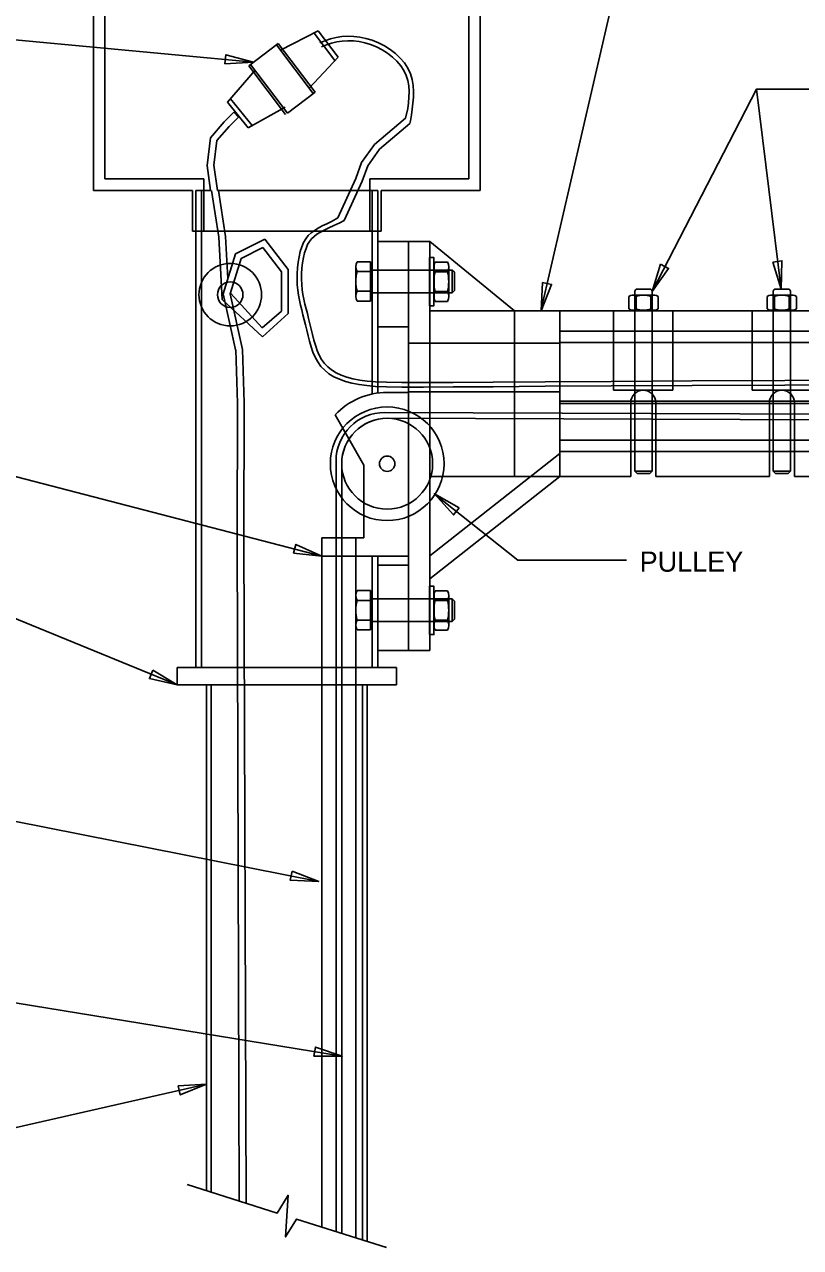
# Model space of a CAD drawing. Extents: x 1299104.6 to 1299141.4, y 239713.3 to 239735.3.
# Drawn here: x 1299115.78 to 1299120.38, y 239723.02 to 239730.29 of the extents above; entities that cross this region are included whole.
import ezdxf

# ---------------------------------------------------------------- set-up
doc = ezdxf.new("R2010")
doc.units = 0
for name, color, linetype in [('Default', 7, 'Continuous'), ('DIM TXT', 7, 'Continuous'), ('Level 3', 7, 'Continuous'), ('Level 5', 7, 'Continuous'), ('Level 6', 7, 'Continuous'), ('Level 8', 7, 'Continuous')]:
    doc.layers.add(name, color=color, linetype=linetype)

# ---------------------------------------------------------------- blocks, each defined once
blk = doc.blocks.new('BOLTS')
at = {"layer": 'Default'}
for p, q in [((-1.5, 0), (-1.5, 17.41)), ((-1.1, 17.81), (1.1, 17.81)), ((1.5, 17.41), (1.5, 0)), ((-1.95, 16.76), (1.95, 16.76)), ((-1.3, 16.52), (-1.3, 14.31)), ((1.3, 16.52), (1.3, 14.31)), ((1.95, 14.07), (-1.95, 14.07)), ((-1.5, -14.24), (-1.5, 0)), ((1.5, 0), (1.5, -14.24)), ((-1.5, -14.24), (1.5, -14.24)), ((-1.1, -14.64), (-1.5, -14.24)), ((1.1, -14.64), (-1.1, -14.64)), ((1.5, -14.24), (1.1, -14.64))]:
    blk.add_line(p, q, dxfattribs=at)
for points in [[(-2.6, 14.31), (-2.6, 16.52)], [(2.6, 16.52), (2.6, 14.31)]]:
    blk.add_lwpolyline(points, dxfattribs=at)
for centre, radius, start, end in [((-1.1, 17.41), 0.4, 90, 180), ((1.1, 17.41), 0.4, 0, 90), ((-1.95, 15.76), 1, 49.4687, 130.5313), ((0, 13.12), 3.64, 69.0802, 110.9198), ((1.95, 15.76), 1, 49.4687, 130.5314), ((-1.95, 15.07), 1, 229.4687, 310.5314), ((0, 17.71), 3.64, 249.0802, 290.9198), ((1.95, 15.07), 1, 229.4687, 310.5313)]:
    blk.add_arc(centre, radius, start, end, dxfattribs=at)

msp = doc.modelspace()

# ---------------------------------------------------------------- linework, layer by layer
at = {"layer": 'Level 3'}
for p, q in [((1299116.1867, 239729.3002), (1299116.1867, 239730.9202)), ((1299116.2542, 239729.3677), (1299116.2542, 239730.9202)), ((1299118.4142, 239729.3677), (1299118.4142, 239730.9202)), ((1299118.4817, 239729.3002), (1299118.4817, 239730.9202)), ((1299117.2964, 239730.1324), (1299117.5205, 239730.2472)), ((1299117.4961, 239730.2347), (1299117.6196, 239730.0715)), ((1299117.5205, 239730.2472), (1299117.6382, 239730.0916)), ((1299117.2831, 239730.1725), (1299117.1077, 239730.0397)), ((1299117.2723, 239730.1643), (1299117.491, 239729.8753)), ((1299117.2831, 239730.1725), (1299117.5018, 239729.8835)), ((1299117.1184, 239730.0479), (1299117.3371, 239729.7589)), ((1299117.4669, 239729.9072), (1299117.6382, 239730.0916)), ((1299117.1459, 239730.0141), (1299116.9815, 239729.8234)), ((1299117.1077, 239730.0397), (1299117.3263, 239729.7507)), ((1299116.9994, 239729.8442), (1299117.1289, 239729.6857)), ((1299117.5018, 239729.8835), (1299117.3371, 239729.7589)), ((1299116.9621, 239729.7081), (1299117.0186, 239729.7645)), ((1299116.9815, 239729.8234), (1299117.105, 239729.6723)), ((1299117.0186, 239729.7645), (1299117.0472, 239729.7359)), ((1299117.3246, 239729.7953), (1299117.105, 239729.6723)), ((1299116.9918, 239729.6805), (1299117.0472, 239729.7359)), ((1299116.8602, 239729.4488), (1299116.8799, 239729.6128)), ((1299116.9186, 239729.5957), (1299116.9918, 239729.6805)), ((1299116.901, 239729.4493), (1299116.9186, 239729.5957)), ((1299116.8814, 239729.3002), (1299116.8602, 239729.4488)), ((1299116.9223, 239729.3002), (1299116.901, 239729.4493)), ((1299116.8419, 239729.3677), (1299116.2542, 239729.3677)), ((1299116.8419, 239729.0572), (1299116.8419, 239729.3677)), ((1299117.8265, 239729.0572), (1299117.8265, 239729.3677)), ((1299118.4142, 239729.3677), (1299117.8265, 239729.3677)), ((1299116.7744, 239729.3002), (1299116.1867, 239729.3002)), ((1299116.7744, 239729.0572), (1299116.7744, 239729.3002)), ((1299116.8814, 239729.3002), (1299116.7942, 239729.3002)), ((1299116.7942, 239729.3002), (1299116.7942, 239726.4653)), ((1299116.8269, 239729.3002), (1299116.8269, 239726.4653)), ((1299116.9301, 239729.0213), (1299116.8864, 239729.3002)), ((1299117.8742, 239729.3002), (1299116.9223, 239729.3002)), ((1299116.9704, 239729.0256), (1299116.9274, 239729.3002)), ((1299117.8416, 239729.3002), (1299117.8416, 239728.0908)), ((1299117.8742, 239729.3002), (1299117.8742, 239728.0964)), ((1299117.894, 239729.0572), (1299117.894, 239729.3002)), ((1299118.4817, 239729.3002), (1299117.894, 239729.3002)), ((1299117.894, 239729.0572), (1299116.7744, 239729.0572)), ((1299116.9506, 239728.6512), (1299116.9301, 239729.0213)), ((1299116.9842, 239728.7771), (1299116.9704, 239729.0256)), ((1299117.0288, 239728.9234), (1299117.2042, 239729.0109)), ((1299117.0625, 239728.8949), (1299117.1923, 239728.9598)), ((1299117.1923, 239728.9598), (1299117.302, 239728.8165)), ((1299117.2042, 239729.0109), (1299117.3425, 239728.8302)), ((1299118.0557, 239728.9965), (1299117.8742, 239728.9965)), ((1299118.0557, 239726.5665), (1299118.0557, 239728.9965)), ((1299118.1826, 239728.9965), (1299118.0557, 239728.9965)), ((1299118.1826, 239728.9965), (1299118.6854, 239728.5854)), ((1299118.1826, 239726.5665), (1299118.1826, 239728.9965)), ((1299116.9566, 239728.6864), (1299117.0288, 239728.9234)), ((1299116.9984, 239728.6848), (1299117.0625, 239728.8949)), ((1299117.302, 239728.8165), (1299117.302, 239728.5832)), ((1299117.3425, 239728.8302), (1299117.3425, 239728.5681)), ((1299117.7433, 239728.6717), (1299117.7433, 239728.847)), ((1299117.7527, 239728.8178), (1299117.8311, 239728.8178)), ((1299117.8308, 239728.6424), (1299117.8308, 239728.8763)), ((1299117.8416, 239728.8516), (1299117.8308, 239728.8516)), ((1299117.8416, 239728.8268), (1299118.3166, 239728.8268)), ((1299118.2083, 239728.8454), (1299118.2083, 239728.67)), ((1299118.215, 239728.8161), (1299118.2887, 239728.8161)), ((1299118.2955, 239728.67), (1299118.2955, 239728.8454)), ((1299118.3166, 239728.6918), (1299118.3166, 239728.8268)), ((1299118.3166, 239728.8268), (1299118.3301, 239728.8133)), ((1299118.3301, 239728.8133), (1299118.3301, 239728.7053)), ((1299117.0322, 239728.3457), (1299116.9566, 239728.6864)), ((1299117.0718, 239728.3545), (1299116.9984, 239728.6848)), ((1299117.1879, 239728.4843), (1299117.0012, 239728.6874)), ((1299117.7527, 239728.7009), (1299117.8311, 239728.7009)), ((1299117.8416, 239728.6671), (1299117.8308, 239728.6671)), ((1299118.3166, 239728.6918), (1299117.8416, 239728.6918)), ((1299118.215, 239728.6992), (1299118.2887, 239728.6992)), ((1299118.3166, 239728.6918), (1299118.3301, 239728.7053)), ((1299117.1898, 239728.4308), (1299116.9506, 239728.6512)), ((1299117.302, 239728.5832), (1299117.1879, 239728.4843)), ((1299117.3425, 239728.5681), (1299117.1898, 239728.4308)), ((1299118.1826, 239728.5854), (1299120.6126, 239728.5854)), ((1299118.6854, 239727.5999), (1299118.6854, 239728.5854)), ((1299118.9548, 239727.5999), (1299118.9548, 239728.5854)), ((1299119.2745, 239728.5854), (1299119.2745, 239728.1129)), ((1299119.626, 239728.5854), (1299119.626, 239728.1129)), ((1299120.098, 239728.5854), (1299120.098, 239728.1129)), ((1299118.0557, 239728.4902), (1299117.8742, 239728.4902)), ((1299117.93, 239728.1001), (1299118.0557, 239728.1001)), ((1299119.2745, 239728.1129), (1299119.626, 239728.1129)), ((1299119.376, 239728.1129), (1299119.5245, 239728.1129)), ((1299120.098, 239728.1129), (1299120.4495, 239728.1129)), ((1299119.376, 239727.5999), (1299119.376, 239728.0387)), ((1299119.5245, 239727.5999), (1299119.5245, 239728.0387)), ((1299120.1995, 239727.5999), (1299120.1995, 239728.0387)), ((1299120.348, 239727.5999), (1299120.348, 239728.0387)), ((1299119.5245, 239727.7484), (1299119.376, 239727.7484)), ((1299120.348, 239727.7484), (1299120.1995, 239727.7484)), ((1299118.1826, 239726.9924), (1299118.9548, 239727.5999)), ((1299118.1826, 239727.5999), (1299119.376, 239727.5999)), ((1299119.5245, 239727.5999), (1299120.1995, 239727.5999)), ((1299120.348, 239727.5999), (1299120.6126, 239727.5999)), ((1299117.5427, 239727.1281), (1299117.5427, 239727.2361)), ((1299117.7433, 239727.2361), (1299117.7433, 239723.0777)), ((1299117.5427, 239727.1281), (1299117.5427, 239723.1411)), ((1299117.5427, 239727.1281), (1299117.7433, 239727.1281)), ((1299117.8416, 239727.1281), (1299117.8416, 239726.4653)), ((1299117.8742, 239727.1281), (1299117.8742, 239726.4653)), ((1299118.0557, 239727.0728), (1299117.8742, 239727.0728)), ((1299117.8308, 239726.6894), (1299117.8308, 239726.9232)), ((1299117.7433, 239726.7186), (1299117.7433, 239726.8939)), ((1299117.7527, 239726.8647), (1299117.8311, 239726.8647)), ((1299117.8416, 239726.8985), (1299117.8308, 239726.8985)), ((1299117.8416, 239726.8738), (1299118.3166, 239726.8738)), ((1299118.2083, 239726.8923), (1299118.2083, 239726.7169)), ((1299118.215, 239726.8631), (1299118.2887, 239726.8631)), ((1299118.2955, 239726.7169), (1299118.2955, 239726.8923)), ((1299118.3166, 239726.7388), (1299118.3166, 239726.8738)), ((1299118.3166, 239726.8738), (1299118.3301, 239726.8603)), ((1299118.3301, 239726.8603), (1299118.3301, 239726.7523)), ((1299117.7527, 239726.7478), (1299117.8311, 239726.7478)), ((1299117.8416, 239726.7141), (1299117.8308, 239726.7141)), ((1299118.3166, 239726.7388), (1299117.8416, 239726.7388)), ((1299118.215, 239726.7461), (1299118.2887, 239726.7461)), ((1299118.3166, 239726.7388), (1299118.3301, 239726.7523)), ((1299118.0557, 239726.5665), (1299117.8742, 239726.5665)), ((1299118.1826, 239726.5665), (1299118.0557, 239726.5665)), ((1299117.986, 239726.4653), (1299116.6824, 239726.4653)), ((1299116.6824, 239726.3627), (1299116.6824, 239726.4653)), ((1299117.986, 239726.4653), (1299117.986, 239726.3627)), ((1299117.986, 239726.3627), (1299116.6824, 239726.3627)), ((1299116.8576, 239726.3627), (1299116.8576, 239723.3577)), ((1299116.8846, 239726.3627), (1299116.8846, 239723.3491)), ((1299117.7839, 239726.3627), (1299117.7839, 239723.0649)), ((1299117.8109, 239726.3627), (1299117.8109, 239723.0564))]:
    msp.add_line(p, q, dxfattribs=at)
for points in [[(1299117.5296, 239730.1771), (1299117.5604, 239730.1894), (1299117.593, 239730.1999), (1299117.6263, 239730.208), (1299117.6605, 239730.2134), (1299117.6955, 239730.2159), (1299117.7311, 239730.2151), (1299117.7674, 239730.211), (1299117.8041, 239730.2031), (1299117.8411, 239730.1916), (1299117.8777, 239730.1765), (1299117.9133, 239730.1582), (1299117.9472, 239730.1369), (1299117.9789, 239730.1128), (1299118.0077, 239730.0862), (1299118.0328, 239730.0571), (1299118.0534, 239730.0256), (1299118.0687, 239729.9924), (1299118.0789, 239729.9582), (1299118.0847, 239729.9233), (1299118.0868, 239729.8882), (1299118.0861, 239729.8529), (1299118.0832, 239729.8177), (1299118.0788, 239729.7826), (1299118.0736, 239729.7479), (1299118.0681, 239729.7133), (1299118.0655, 239729.6983)], [(1299117.5396, 239730.152), (1299117.5696, 239730.164), (1299117.6003, 239730.1739), (1299117.6316, 239730.1815), (1299117.6636, 239730.1865), (1299117.6962, 239730.1888), (1299117.7293, 239730.1882), (1299117.763, 239730.1843), (1299117.7973, 239730.177), (1299117.8319, 239730.1661), (1299117.8664, 239730.1519), (1299117.8999, 239730.1347), (1299117.9319, 239730.1147), (1299117.9615, 239730.0921), (1299117.9882, 239730.0674), (1299118.0112, 239730.0408), (1299118.0297, 239730.0125), (1299118.0434, 239729.9829), (1299118.0526, 239729.9521), (1299118.0578, 239729.9203), (1299118.0598, 239729.8876), (1299118.0591, 239729.8543), (1299118.0563, 239729.8205), (1299118.0521, 239729.7863), (1299118.0393, 239729.7292), (1299118.0521, 239729.7863), (1299118.0521, 239729.7863), (1299118.0393, 239729.7292)], [(1299116.8799, 239729.6128), (1299116.9621, 239729.7081)], [(1299117.6374, 239729.1374), (1299117.744, 239729.3706), (1299117.7783, 239729.4647), (1299117.8545, 239729.5721), (1299118.0393, 239729.7292)], [(1299117.6742, 239729.1205), (1299117.7816, 239729.3552), (1299117.8145, 239729.4457), (1299117.8846, 239729.5445), (1299118.0655, 239729.6983)], [(1299117.6026, 239729.1164), (1299117.6026, 239729.1164), (1299117.6374, 239729.1374), (1299117.6026, 239729.1164), (1299117.572, 239729.1021), (1299117.5444, 239729.0887), (1299117.5197, 239729.0756), (1299117.4977, 239729.0621), (1299117.4782, 239729.0474), (1299117.4612, 239729.0311), (1299117.4463, 239729.0123), (1299117.4335, 239728.9905), (1299117.4226, 239728.9651), (1299117.4136, 239728.9366), (1299117.4064, 239728.9057), (1299117.4009, 239728.8731), (1299117.3972, 239728.8394), (1299117.3952, 239728.8053), (1299117.3949, 239728.7715), (1299117.3963, 239728.7386), (1299117.3992, 239728.7071), (1299117.4035, 239728.6769), (1299117.4089, 239728.6475), (1299117.4152, 239728.6187), (1299117.4223, 239728.59), (1299117.4297, 239728.561), (1299117.4374, 239728.5315), (1299117.445, 239728.5009), (1299117.4525, 239728.4692), (1299117.4601, 239728.4367), (1299117.4685, 239728.4039), (1299117.4779, 239728.3714), (1299117.489, 239728.3397), (1299117.5022, 239728.3093), (1299117.518, 239728.2808), (1299117.5367, 239728.2547), (1299117.5589, 239728.2315), (1299117.5845, 239728.2111), (1299117.6135, 239728.1933), (1299117.646, 239728.1782), (1299117.6818, 239728.1654), (1299117.7209, 239728.1549), (1299117.7633, 239728.1466), (1299117.809, 239728.1402), (1299117.8598, 239728.1358), (1299117.9252, 239728.133), (1299118.0166, 239728.1316), (1299118.1453, 239728.1314), (1299118.3227, 239728.1323), (1299118.5602, 239728.1339), (1299118.8691, 239728.1361), (1299119.2609, 239728.1386), (1299119.7409, 239728.1412), (1299120.2913, 239728.1437), (1299120.8881, 239728.1458)], [(1299117.6742, 239729.1205), (1299117.6479, 239729.1079), (1299117.6141, 239729.092), (1299117.5836, 239729.0777), (1299117.5566, 239729.0646), (1299117.5331, 239729.0521), (1299117.5129, 239729.0397), (1299117.4957, 239729.0268), (1299117.4812, 239729.0129), (1299117.4687, 239728.9971), (1299117.4577, 239728.9783), (1299117.448, 239728.9557), (1299117.4396, 239728.9295), (1299117.4328, 239728.9004), (1299117.4277, 239728.8694), (1299117.4241, 239728.8371), (1299117.4222, 239728.8044), (1299117.4219, 239728.7719), (1299117.4232, 239728.7403), (1299117.426, 239728.7102), (1299117.4301, 239728.6812), (1299117.4354, 239728.6529), (1299117.4415, 239728.6248), (1299117.4484, 239728.5965), (1299117.4559, 239728.5678), (1299117.4635, 239728.5381), (1299117.4712, 239728.5073), (1299117.4787, 239728.4754), (1299117.4863, 239728.4431), (1299117.4945, 239728.411), (1299117.5037, 239728.3796), (1299117.5142, 239728.3495), (1299117.5265, 239728.3212), (1299117.5408, 239728.2953), (1299117.5575, 239728.272), (1299117.5771, 239728.2515), (1299117.6, 239728.2332), (1299117.6263, 239728.2172), (1299117.6563, 239728.2032), (1299117.6898, 239728.1912), (1299117.727, 239728.1812), (1299117.7678, 239728.1732), (1299117.8121, 239728.1671), (1299117.8616, 239728.1627), (1299117.926, 239728.1599), (1299118.0168, 239728.1586), (1299118.1452, 239728.1584), (1299118.3225, 239728.1593), (1299118.56, 239728.1609), (1299118.8689, 239728.1631), (1299119.2607, 239728.1656), (1299119.7408, 239728.1682), (1299120.2912, 239728.1707), (1299120.888, 239728.1728)], [(1299117.7527, 239728.8763), (1299117.8308, 239728.8763)], [(1299117.8416, 239728.8516), (1299117.8416, 239728.6671)], [(1299118.215, 239728.8746), (1299118.2887, 239728.8746)], [(1299117.8308, 239728.6424), (1299117.7527, 239728.6424)], [(1299118.2887, 239728.6408), (1299118.215, 239728.6408)], [(1299117.7527, 239726.9232), (1299117.8308, 239726.9232)], [(1299118.215, 239726.9215), (1299118.2887, 239726.9215)], [(1299117.8416, 239726.8985), (1299117.8416, 239726.7141)], [(1299117.8308, 239726.6894), (1299117.7527, 239726.6894)], [(1299118.2887, 239726.6877), (1299118.215, 239726.6877)]]:
    msp.add_lwpolyline(points, dxfattribs=at)
for points in [[(1299118.1816, 239728.6143), (1299118.1816, 239728.901), (1299118.2073, 239728.901), (1299118.2073, 239728.6143)], [(1299118.1816, 239726.6612), (1299118.1816, 239726.948), (1299118.2073, 239726.948), (1299118.2073, 239726.6612)]]:
    msp.add_lwpolyline(points, close=True, dxfattribs=at)
for centre, radius in [((1299116.9979, 239728.6805), 0.1858), ((1299116.9979, 239728.6805), 0.0759), ((1299117.93, 239727.6762), 0.0459)]:
    msp.add_circle(centre, radius, dxfattribs=at)
for centre, radius, start, end in [((1299117.7932, 239728.847), 0.0499, 144.1655, 215.8345), ((1299117.9288, 239728.7593), 0.1855, 161.6338, 198.3662), ((1299118.2749, 239728.8454), 0.0667, 153.9914, 206.0086), ((1299118.4647, 239728.7577), 0.2565, 166.826, 193.174), ((1299118.2288, 239728.8454), 0.0667, 333.9913, 26.00868), ((1299118.039, 239728.7577), 0.2565, 346.826, 13.17401), ((1299117.7932, 239728.6717), 0.0499, 144.1654, 215.8346), ((1299118.2749, 239728.67), 0.0667, 153.9913, 206.0087), ((1299118.2288, 239728.67), 0.0667, 333.9914, 26.00863), ((1299119.4503, 239728.0387), 0.0742, 0, 180), ((1299120.2738, 239728.0387), 0.0742, 0, 180), ((1299117.93, 239727.6762), 0.27, 89.81051, 180), ((1299117.7932, 239726.8939), 0.0499, 144.1655, 215.8345), ((1299118.2749, 239726.8923), 0.0667, 153.9914, 206.0086), ((1299118.2288, 239726.8923), 0.0667, 333.9913, 26.00868), ((1299117.9288, 239726.8063), 0.1855, 161.6338, 198.3662), ((1299118.4647, 239726.8046), 0.2565, 166.826, 193.174), ((1299118.039, 239726.8046), 0.2565, 346.826, 13.17401), ((1299117.7932, 239726.7186), 0.0499, 144.1654, 215.8346), ((1299118.2749, 239726.7169), 0.0667, 153.9913, 206.0087), ((1299118.2288, 239726.7169), 0.0667, 333.9914, 26.00863)]:
    msp.add_arc(centre, radius, start, end, dxfattribs=at)
at = {"layer": 'Level 5'}
for p, q in [((1299117.0408, 239728.0367), (1299117.0313, 239728.3536)), ((1299117.0813, 239728.0376), (1299117.0718, 239728.3545)), ((1299117.0388, 239727.2436), (1299117.0408, 239728.0377)), ((1299117.0793, 239727.2435), (1299117.0813, 239728.0376)), ((1299117.0516, 239723.2963), (1299117.0388, 239727.2433)), ((1299117.0921, 239723.2835), (1299117.0793, 239727.2435))]:
    msp.add_line(p, q, dxfattribs=at)
at = {"layer": 'Level 6'}
for p, q in [((1299120.6126, 239728.4639), (1299118.9548, 239728.4639)), ((1299118.0557, 239728.393), (1299118.9548, 239728.393)), ((1299120.6126, 239728.3964), (1299118.9548, 239728.3964)), ((1299118.0557, 239728.1029), (1299118.9548, 239728.1029)), ((1299124.3548, 239728.0482), (1299118.9548, 239728.0482)), ((1299124.3548, 239728.0347), (1299118.9548, 239728.0347)), ((1299117.7923, 239727.6681), (1299117.6213, 239727.9667)), ((1299117.9141, 239727.98), (1299124.7722, 239727.9573)), ((1299117.9309, 239727.9462), (1299124.7553, 239727.9236)), ((1299120.6126, 239727.8159), (1299118.9548, 239727.8159)), ((1299118.1826, 239727.1298), (1299118.9548, 239727.7373)), ((1299120.6126, 239727.7484), (1299118.9548, 239727.7484)), ((1299117.6262, 239727.6931), (1299117.6262, 239723.1147)), ((1299117.66, 239727.6762), (1299117.66, 239723.1041)), ((1299117.7923, 239727.2361), (1299117.7923, 239727.6681)), ((1299117.5427, 239727.2361), (1299117.7923, 239727.2361)), ((1299117.5427, 239727.1281), (1299118.0557, 239727.1281))]:
    msp.add_line(p, q, dxfattribs=at)
for radius in [0.3375, 0.27]:
    msp.add_circle((1299117.93, 239727.6762), radius, dxfattribs=at)
for centre, radius, start, end in [((1299117.93, 239727.6762), 0.4239, 90, 136.74441), ((1299117.9131, 239727.6931), 0.2869, 89.81051, 180)]:
    msp.add_arc(centre, radius, start, end, dxfattribs=at)
at = {"layer": 'Level 8'}
for points in [[(1299118.8433, 239728.5854), (1299119.272, 239730.4433), (1299120.8021, 239730.4433)], [(1299117.1354, 239730.0607), (1299117.1354, 239730.0607), (1299114.8082, 239730.2803), (1299112.852, 239730.2803)], [(1299119.5029, 239728.6996), (1299119.5029, 239728.6996), (1299120.1241, 239729.9022), (1299120.793, 239729.9022)], [(1299120.2704, 239728.7139), (1299120.1241, 239729.9022), (1299120.8021, 239729.9022)], [(1299117.5427, 239727.1281), (1299113.6708, 239728.1331), (1299111.4228, 239728.1331), (1299111.4351, 239728.1331)], [(1299118.2098, 239727.4983), (1299118.2098, 239727.4983), (1299118.7066, 239727.1026), (1299119.3507, 239727.1026)], [(1299116.6824, 239726.3627), (1299114.9168, 239727.086)], [(1299117.5236, 239725.1938), (1299113.493, 239725.993), (1299111.3748, 239725.993)], [(1299117.6635, 239724.1563), (1299117.6635, 239724.1563), (1299114.3474, 239724.6972), (1299111.173, 239724.6972)], [(1299116.8576, 239723.9908), (1299115.4379, 239723.667), (1299111.4055, 239723.667)], [(1299116.7432, 239723.3938), (1299117.277, 239723.2251), (1299117.3418, 239723.3305), (1299117.3267, 239723.0836), (1299117.3914, 239723.1889), (1299117.9253, 239723.0202)]]:
    msp.add_lwpolyline(points, dxfattribs=at)
for points in [[(1299116.9665, 239730.0521), (1299116.9725, 239730.1061), (1299117.1354, 239730.0607)], [(1299119.5529, 239728.8611), (1299119.6015, 239728.8369), (1299119.5029, 239728.6996)], [(1299120.2204, 239728.8745), (1299120.2742, 239728.8822), (1299120.2707, 239728.7132)], [(1299118.8534, 239728.7536), (1299118.9065, 239728.7419), (1299118.8438, 239728.5849)], [(1299118.3578, 239727.4152), (1299118.324, 239727.3727), (1299118.2103, 239727.4977)], [(1299117.3745, 239727.1447), (1299117.3885, 239727.1973), (1299117.5427, 239727.1281)], [(1299116.5381, 239726.4506), (1299116.5176, 239726.4003), (1299116.6824, 239726.3627)], [(1299117.366, 239725.2551), (1299117.3547, 239725.2019), (1299117.5236, 239725.1938)], [(1299117.4945, 239724.1575), (1299117.5036, 239724.2111), (1299117.6635, 239724.1563)], [(1299116.6889, 239723.9799), (1299116.7011, 239723.927), (1299116.8576, 239723.9908)]]:
    msp.add_lwpolyline(points, close=True, dxfattribs=at)

# ---------------------------------------------------------------- block references
at = {"layer": 'Level 3', "xscale": 0.03374999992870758, "yscale": 0.0337499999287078}
for p in [(1299119.4523, 239728.1129), (1299120.2736, 239728.1129)]:
    msp.add_blockref('BOLTS', p, dxfattribs=at)

# ---------------------------------------------------------------- texts
at = {"layer": 'DIM TXT'}
msp.add_text('PULLEY', height=0.12, dxfattribs=at).set_placement((1299119.4293, 239727.0347))

doc.saveas('drawing.dxf')
